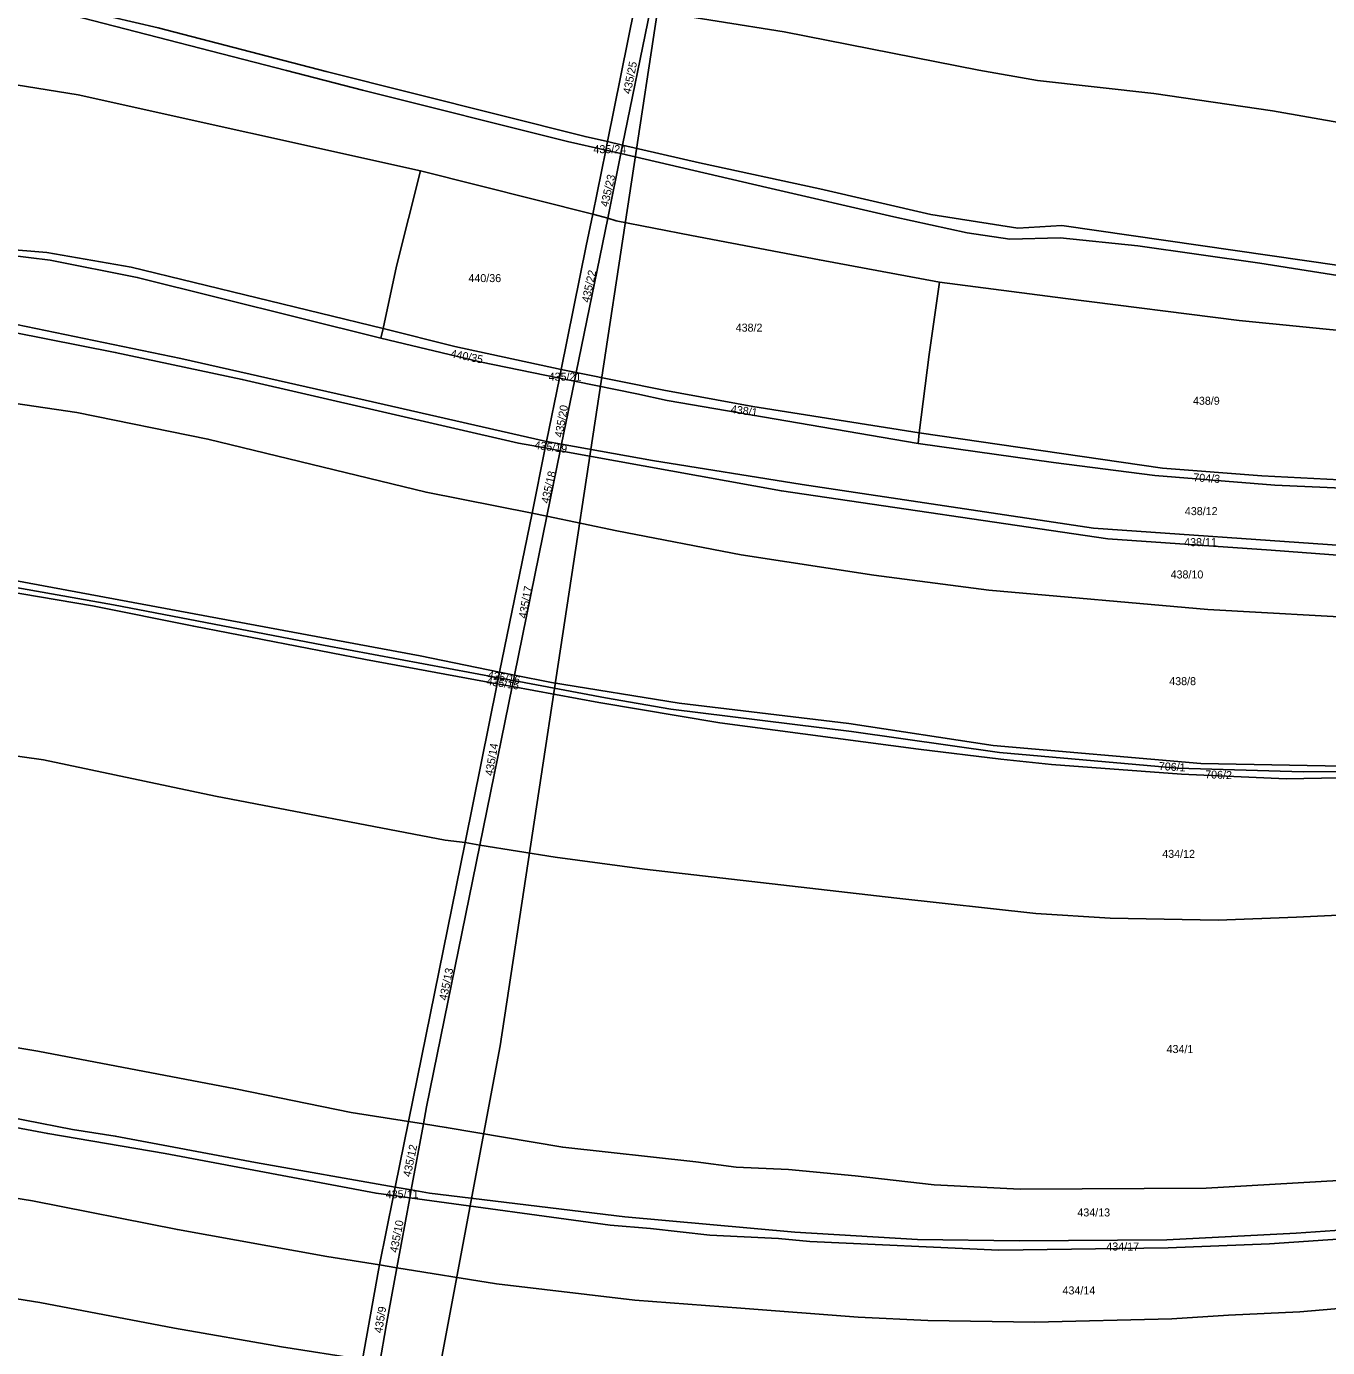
# Model space of a CAD drawing. Extents: x -629983 to -626385, y -1072828 to -1067897.
# Drawn here: x -628398.5 to -627910.7, y -1070643.4 to -1070148.2 of the extents above; entities that cross this region are included whole.
import ezdxf

# ---------------------------------------------------------------- set-up
doc = ezdxf.new("R2010")
doc.units = 0
for name, color, linetype in [('Cesty', 7, 'Continuous'), ('Parcela nároku', 7, 'Continuous'), ('Parcelní číslo', 7, 'Continuous')]:
    doc.layers.add(name, color=color, linetype=linetype)

msp = doc.modelspace()

# ---------------------------------------------------------------- linework, layer by layer
at = {"layer": 'Cesty'}
msp.add_lwpolyline([(-628278.28, -1070828.99), (-628259.19, -1070734.89), (-628220.88, -1070530.25), (-628148.19, -1070051.86), (-628124.88, -1069886.45), (-628121.14, -1069861.86), (-628117.17, -1069852.4), (-628107.82, -1069847.56)], dxfattribs=at)
at = {"layer": 'Parcela nároku'}
for points in [[(-627852.52, -1070193.73), (-627931.37, -1070179.87), (-627975.88, -1070173.38), (-628019.4, -1070168.39), (-628041.43, -1070164.52), (-628114.45, -1070150.16), (-628164.7, -1070142.19), (-628155.63, -1070097.66), (-628130.17, -1070104.96), (-628104.27, -1070109.98), (-628049.15, -1070120.03), (-628018.31, -1070124.92), (-627989.36, -1070130.86), (-627971.32, -1070129.6), (-627953.47, -1070132.37), (-627927.69, -1070135.69), (-627870.76, -1070142.6)], [(-628697.14, -1070105.5), (-628669.73, -1070105.5), (-628645.55, -1070106.32), (-628620.29, -1070107.74), (-628548.7, -1070115.17), (-628493.54, -1070122.93), (-628470.6, -1070125.72), (-628412.78, -1070135.53), (-628392.25, -1070138.74), (-628349.08, -1070148.7), (-628286.11, -1070165.03), (-628189.07, -1070189.45), (-628180.65, -1070191.36), (-628181.31, -1070194.54), (-628195.6, -1070191.34), (-628272.47, -1070172.11), (-628301.01, -1070164.65), (-628377.52, -1070144.99), (-628400.65, -1070140.75), (-628466.36, -1070130.15), (-628560.91, -1070117.14), (-628623.23, -1070110.99), (-628654.47, -1070108.86), (-628697.25, -1070109.21)], [(-628697.25, -1070109.21), (-628654.47, -1070108.86), (-628623.23, -1070110.99), (-628560.91, -1070117.14), (-628466.36, -1070130.15), (-628400.65, -1070140.75), (-628377.52, -1070144.99), (-628301.01, -1070164.65), (-628272.47, -1070172.11), (-628195.6, -1070191.34), (-628181.31, -1070194.54), (-628186.19, -1070218.59), (-628250.78, -1070202.28), (-628379.11, -1070173.77), (-628421.82, -1070167.01), (-628468.03, -1070161.59), (-628516.64, -1070158.65), (-628589.02, -1070154.96), (-628707.96, -1070153.76)], [(-628170.51, -1070141.27), (-628180.65, -1070191.36), (-628189.07, -1070189.45), (-628286.11, -1070165.03), (-628349.08, -1070148.7), (-628392.25, -1070138.74)], [(-627852.52, -1070193.73), (-627931.37, -1070179.87), (-627975.88, -1070173.38), (-628019.4, -1070168.39), (-628041.43, -1070164.52), (-628114.45, -1070150.16), (-628164.7, -1070142.19), (-628175, -1070192.75), (-628146.13, -1070199.31), (-628101.07, -1070209.03), (-628059.41, -1070218.64), (-628026.82, -1070223.84), (-628010.32, -1070222.78), (-627867.35, -1070243.48)], [(-627872.06, -1070246.99), (-627936.13, -1070236.87), (-627981.78, -1070230.48), (-628010.99, -1070227.44), (-628029.83, -1070227.91), (-628045.76, -1070225.52), (-628073.29, -1070219.58), (-628120.92, -1070208.51), (-628175.63, -1070195.81), (-628180.56, -1070220), (-628177.36, -1070221.02), (-628149.11, -1070226.54), (-628101.18, -1070235.71), (-628056.15, -1070244.07), (-628008.92, -1070250.2), (-627943.87, -1070258.43), (-627852.12, -1070267.55)], [(-627872.06, -1070246.99), (-627936.13, -1070236.87), (-627981.78, -1070230.48), (-628010.99, -1070227.44), (-628029.83, -1070227.91), (-628045.76, -1070225.52), (-628073.29, -1070219.58), (-628120.92, -1070208.51), (-628175.63, -1070195.81), (-628175, -1070192.75), (-628146.13, -1070199.31), (-628101.07, -1070209.03), (-628059.41, -1070218.64), (-628026.82, -1070223.84), (-628010.32, -1070222.78), (-627867.35, -1070243.48)], [(-628706.32, -1070228.2), (-628676.43, -1070226.93), (-628641.43, -1070225.97), (-628548.86, -1070228.15), (-628496.37, -1070229.17), (-628472.75, -1070229.44), (-628405.88, -1070233.81), (-628389.6, -1070235.8), (-628356.96, -1070242.24), (-628265.56, -1070264.98), (-628228.53, -1070273.87), (-628198.66, -1070279.99), (-628203.49, -1070303.75), (-628271.49, -1070288.24), (-628340.63, -1070272.61), (-628402.14, -1070259.92), (-628441.52, -1070255.31), (-628483.88, -1070253.57), (-628553.7, -1070253.06), (-628664.36, -1070255.18), (-628699.47, -1070256.47)], [(-628718.01, -1070289.28), (-628654.01, -1070286.5), (-628619.64, -1070286.58), (-628545.91, -1070283.54), (-628494.55, -1070281.54), (-628438.22, -1070284.3), (-628379.6, -1070292.88), (-628330.41, -1070302.87), (-628248.65, -1070322.77), (-628208.94, -1070330.57), (-628203.99, -1070306.2), (-628214, -1070304.38), (-628317.59, -1070280.52), (-628365.18, -1070270.35), (-628403.66, -1070262.78), (-628433.52, -1070259), (-628452.82, -1070257.33), (-628510.86, -1070255.71), (-628594.38, -1070256.49), (-628664.77, -1070258.22), (-628698.91, -1070259.7)], [(-628718.01, -1070289.28), (-628654.01, -1070286.5), (-628619.64, -1070286.58), (-628545.91, -1070283.54), (-628494.55, -1070281.54), (-628438.22, -1070284.3), (-628379.6, -1070292.88), (-628330.41, -1070302.87), (-628248.65, -1070322.77), (-628208.94, -1070330.57), (-628221.07, -1070390.29), (-628250.91, -1070384.06), (-628402.82, -1070355.87), (-628428.44, -1070352.58), (-628471.84, -1070348.52), (-628506.06, -1070348.62), (-628535.45, -1070349.59), (-628587.84, -1070353.27), (-628641.1, -1070355.58), (-628669.24, -1070357.52), (-628669.03, -1070360), (-628668.96, -1070361.81), (-628716.27, -1070364.26)], [(-628426.01, -1070356.51), (-628373.76, -1070365.31), (-628335.77, -1070373.02), (-628271.33, -1070385.43), (-628221.94, -1070394.59), (-628234.03, -1070454.14), (-628241.48, -1070453.19), (-628327.58, -1070436.69), (-628392.12, -1070423.1), (-628443.67, -1070415.82)], [(-627830.1, -1070477.74), (-627922.31, -1070482.11), (-627951.66, -1070483.18), (-627992.24, -1070482.47), (-628020, -1070480.64), (-628072.18, -1070474.9), (-628166.82, -1070464.1), (-628200.27, -1070459.64), (-628228.46, -1070455.05), (-628216.36, -1070395.63), (-628183.83, -1070401.66), (-628138.5, -1070409.17), (-628064.04, -1070419.12), (-628033.19, -1070422.86), (-628014.16, -1070424.89), (-627965.43, -1070428.42), (-627926.22, -1070430.23), (-627866.68, -1070429.07)], [(-628437.81, -1070524.99), (-628394.14, -1070532.32), (-628320.09, -1070546.38), (-628276.71, -1070555.23), (-628255.21, -1070558.63), (-628234.03, -1070454.14), (-628241.48, -1070453.19), (-628327.58, -1070436.69), (-628392.12, -1070423.1), (-628443.67, -1070415.82)], [(-627830.1, -1070477.74), (-627922.31, -1070482.11), (-627951.66, -1070483.18), (-627992.24, -1070482.47), (-628020, -1070480.64), (-628072.18, -1070474.9), (-628166.82, -1070464.1), (-628200.27, -1070459.64), (-628228.46, -1070455.05), (-628248.46, -1070553.17), (-628249.63, -1070559.51), (-628241.09, -1070560.87), (-628197.41, -1070568.33), (-628147.55, -1070573.73), (-628132.4, -1070575.73), (-628112.77, -1070576.7), (-628087.81, -1070579.06), (-628058.23, -1070582.4), (-628025.88, -1070584.04), (-627956.15, -1070583.61), (-627880.67, -1070579.28)], [(-628437.81, -1070524.99), (-628394.14, -1070532.32), (-628320.09, -1070546.38), (-628276.71, -1070555.23), (-628255.21, -1070558.63), (-628260.2, -1070583.25), (-628312.58, -1070573.99), (-628365.16, -1070564.13), (-628381.21, -1070561.65), (-628434.99, -1070551.16)], [(-628452.48, -1070551.49), (-628390.46, -1070563.16), (-628346.52, -1070570.66), (-628267.4, -1070585.55), (-628260.85, -1070586.44), (-628266.12, -1070612.44), (-628285.86, -1070609.24), (-628341.85, -1070599.18), (-628396.16, -1070588.43), (-628461.18, -1070577.86)], [(-627886.17, -1070598.06), (-627922.42, -1070600.5), (-627971, -1070603.08), (-628026.25, -1070603.41), (-628064.48, -1070602.87), (-628110.42, -1070600.1), (-628174.13, -1070594.4), (-628247.39, -1070585.51), (-628254.21, -1070584.31), (-628249.63, -1070559.51), (-628241.09, -1070560.87), (-628197.41, -1070568.33), (-628147.55, -1070573.73), (-628132.4, -1070575.73), (-628112.77, -1070576.7), (-628087.81, -1070579.06), (-628058.23, -1070582.4), (-628025.88, -1070584.04), (-627956.15, -1070583.61), (-627880.67, -1070579.28)], [(-628461.18, -1070577.86), (-628396.16, -1070588.43), (-628341.85, -1070599.18), (-628285.86, -1070609.24), (-628266.12, -1070612.44), (-628266.51, -1070614.38), (-628272.51, -1070647.92), (-628302.84, -1070643.17), (-628342.94, -1070636.07), (-628393.47, -1070626.54), (-628442.96, -1070618.68)], [(-627879.61, -1070600.88), (-627932.47, -1070604.52), (-627970.45, -1070606.06), (-628033.95, -1070606.87), (-628104.75, -1070603.7), (-628116.52, -1070602.55), (-628142.22, -1070601.28), (-628164.51, -1070598.79), (-628179.7, -1070597.46), (-628254.76, -1070587.27), (-628259.61, -1070613.49), (-628222.19, -1070619.55), (-628170.37, -1070625.67), (-628130.69, -1070628.69), (-628086.68, -1070632.01), (-628060.6, -1070633.22), (-628020.49, -1070633.87), (-627969.04, -1070632.64), (-627947.86, -1070631.28), (-627921.14, -1070630.03), (-627870.01, -1070625.59)], [(-628272.51, -1070647.92), (-628302.84, -1070643.17), (-628342.94, -1070636.07), (-628393.47, -1070626.54), (-628442.96, -1070618.68), (-628464.05, -1070615.64), (-628486.47, -1070613.85), (-628509.5, -1070612.76), (-628545.74, -1070615.25), (-628593.51, -1070623.9), (-628639.5, -1070632.73), (-628651.77, -1070635.89), (-628709.71, -1070648.87)], [(-627903.25, -1070656.94), (-627969.61, -1070662.08), (-628010.4, -1070663.68), (-628050.69, -1070664.96), (-628095.77, -1070665.28), (-628130.82, -1070663.87), (-628192.91, -1070658.82), (-628232.19, -1070654.23), (-628265.99, -1070648.94), (-628263.64, -1070635.31), (-628259.61, -1070613.49), (-628222.19, -1070619.55), (-628170.37, -1070625.67), (-628130.69, -1070628.69), (-628086.68, -1070632.01), (-628060.6, -1070633.22), (-628020.49, -1070633.87), (-627969.04, -1070632.64), (-627947.86, -1070631.28), (-627921.14, -1070630.03), (-627870.01, -1070625.59)]]:
    msp.add_lwpolyline(points, dxfattribs=at)
for points in [[(-628164.7, -1070142.19), (-628170.51, -1070141.27), (-628180.65, -1070191.36), (-628175, -1070192.75)], [(-628379.11, -1070173.77), (-628250.78, -1070202.28), (-628259.79, -1070238.1), (-628264.77, -1070261.35), (-628359.24, -1070238.39), (-628390.8, -1070232.96), (-628442.26, -1070228.67), (-628466.38, -1070227.31), (-628536.07, -1070225.95), (-628573.86, -1070225.34), (-628641.41, -1070224.05), (-628696.79, -1070225.17), (-628706.68, -1070225.65), (-628706.32, -1070228.2), (-628709.82, -1070228.71), (-628714.51, -1070190.29), (-628718.85, -1070154.67), (-628707.96, -1070153.76), (-628589.02, -1070154.96), (-628516.64, -1070158.65), (-628468.03, -1070161.59), (-628421.82, -1070167.01)], [(-628181.31, -1070194.54), (-628180.65, -1070191.36), (-628175, -1070192.75), (-628175.63, -1070195.81)], [(-628175.63, -1070195.81), (-628181.31, -1070194.54), (-628186.19, -1070218.59), (-628180.56, -1070220)], [(-628250.78, -1070202.28), (-628186.19, -1070218.59), (-628188.6, -1070230.48), (-628198.03, -1070276.73), (-628237.85, -1070268.2), (-628264.77, -1070261.35), (-628259.79, -1070238.1)], [(-628188.6, -1070230.48), (-628186.19, -1070218.59), (-628180.56, -1070220), (-628192.38, -1070277.89), (-628198.03, -1070276.73)], [(-628101.18, -1070235.71), (-628056.15, -1070244.07), (-628060.11, -1070271.11), (-628063.81, -1070300.51), (-628126.17, -1070290.63), (-628159.48, -1070284.58), (-628192.38, -1070277.89), (-628180.56, -1070220), (-628177.36, -1070221.02), (-628149.11, -1070226.54)], [(-628573.86, -1070225.34), (-628641.41, -1070224.05), (-628696.79, -1070225.17), (-628706.68, -1070225.65), (-628706.32, -1070228.2), (-628676.43, -1070226.93), (-628641.43, -1070225.97), (-628548.86, -1070228.15), (-628496.37, -1070229.17), (-628472.75, -1070229.44), (-628405.88, -1070233.81), (-628389.6, -1070235.8), (-628356.96, -1070242.24), (-628265.56, -1070264.98), (-628264.77, -1070261.35), (-628359.24, -1070238.39), (-628390.8, -1070232.96), (-628442.26, -1070228.67), (-628466.38, -1070227.31), (-628536.07, -1070225.95)], [(-628060.11, -1070271.11), (-628056.15, -1070244.07), (-628008.92, -1070250.2), (-627943.87, -1070258.43), (-627852.12, -1070267.55), (-627857.41, -1070320.6), (-627935.31, -1070316.64), (-627972.58, -1070313.71), (-628063.81, -1070300.51)], [(-628340.63, -1070272.61), (-628271.49, -1070288.24), (-628203.49, -1070303.75), (-628203.99, -1070306.2), (-628214, -1070304.38), (-628317.59, -1070280.52), (-628365.18, -1070270.35), (-628403.66, -1070262.78), (-628433.52, -1070259), (-628452.82, -1070257.33), (-628510.86, -1070255.71), (-628594.38, -1070256.49), (-628664.77, -1070258.22), (-628698.91, -1070259.7), (-628699.47, -1070256.47), (-628664.36, -1070255.18), (-628553.7, -1070253.06), (-628483.88, -1070253.57), (-628441.52, -1070255.31), (-628402.14, -1070259.92)], [(-628264.77, -1070261.35), (-628237.85, -1070268.2), (-628198.03, -1070276.73), (-628198.66, -1070279.99), (-628228.53, -1070273.87), (-628265.56, -1070264.98)], [(-628198.66, -1070279.99), (-628193.03, -1070281.15), (-628197.85, -1070304.82), (-628203.49, -1070303.75)], [(-628198.03, -1070276.73), (-628198.66, -1070279.99), (-628193.03, -1070281.15), (-628192.38, -1070277.89)], [(-628159.48, -1070284.58), (-628126.17, -1070290.63), (-628063.81, -1070300.51), (-628064.17, -1070304.46), (-628158.28, -1070288.4), (-628169.7, -1070285.94), (-628193.03, -1070281.15), (-628192.38, -1070277.89)], [(-627975.41, -1070316.56), (-628013.39, -1070311.63), (-628064.17, -1070304.46), (-628158.28, -1070288.4), (-628169.7, -1070285.94), (-628193.03, -1070281.15), (-628197.85, -1070304.82), (-628163.72, -1070310.89), (-628107.67, -1070319.94), (-627998.49, -1070336.29), (-627905.29, -1070342.7), (-627827.64, -1070345.16), (-627715.35, -1070349), (-627667.5, -1070351.19), (-627663.96, -1070345.7), (-627647.13, -1070331.03), (-627719.77, -1070327.49), (-627789.19, -1070324.83), (-627857.63, -1070323.4), (-627930.45, -1070320.12)], [(-628203.99, -1070306.2), (-628203.49, -1070303.75), (-628197.85, -1070304.82), (-628198.34, -1070307.23)], [(-627998.49, -1070336.29), (-627905.29, -1070342.7), (-627827.64, -1070345.16), (-627715.35, -1070349), (-627667.5, -1070351.19), (-627669.14, -1070353.74), (-627747.72, -1070351.32), (-627834.23, -1070347.87), (-627862.19, -1070347.87), (-627903.57, -1070346.68), (-627931.89, -1070344.45), (-627993.13, -1070340.27), (-628115.46, -1070322.29), (-628198.34, -1070307.23), (-628197.85, -1070304.82), (-628163.72, -1070310.89), (-628107.67, -1070319.94)], [(-627935.31, -1070316.64), (-627857.41, -1070320.6), (-627857.63, -1070323.4), (-627930.45, -1070320.12), (-627975.41, -1070316.56), (-628013.39, -1070311.63), (-628064.17, -1070304.46), (-628063.81, -1070300.51), (-627972.58, -1070313.71)], [(-628208.94, -1070330.57), (-628203.99, -1070306.2), (-628198.34, -1070307.23), (-628203.34, -1070331.74)], [(-627903.57, -1070346.68), (-627931.89, -1070344.45), (-627993.13, -1070340.27), (-628115.46, -1070322.29), (-628198.34, -1070307.23), (-628203.34, -1070331.74), (-628177.12, -1070337.23), (-628130.58, -1070346.23), (-628080.75, -1070353.83), (-628037.7, -1070359.47), (-627955.53, -1070366.72), (-627892.97, -1070370.2), (-627840.14, -1070371.16), (-627807.49, -1070371.09), (-627701.48, -1070374.12), (-627693.61, -1070374.29), (-627674.98, -1070362.82), (-627669.14, -1070353.74), (-627747.72, -1070351.32), (-627834.23, -1070347.87), (-627862.19, -1070347.87)], [(-628221.07, -1070390.29), (-628208.94, -1070330.57), (-628203.34, -1070331.74), (-628215.5, -1070391.4)], [(-628177.12, -1070337.23), (-628130.58, -1070346.23), (-628080.75, -1070353.83), (-628037.7, -1070359.47), (-627955.53, -1070366.72), (-627892.97, -1070370.2), (-627840.14, -1070371.16), (-627807.49, -1070371.09), (-627701.48, -1070374.12), (-627693.61, -1070374.29), (-627709.42, -1070384.02), (-627728.14, -1070388.04), (-627744.07, -1070422.21), (-627744.1, -1070423.1), (-627756.84, -1070422.46), (-627773.24, -1070422.4), (-627898.31, -1070425.56), (-627958.23, -1070424.48), (-628036.03, -1070417.71), (-628090.14, -1070409.45), (-628153.81, -1070401.82), (-628201.61, -1070394.13), (-628215.5, -1070391.4), (-628203.34, -1070331.74)], [(-628428.44, -1070352.58), (-628402.82, -1070355.87), (-628250.91, -1070384.06), (-628221.07, -1070390.29), (-628221.49, -1070392.37), (-628287.16, -1070380.06), (-628365.88, -1070365.05), (-628421.56, -1070355.07), (-628473.35, -1070350.78), (-628501.58, -1070350.88), (-628529.06, -1070351.77), (-628592.68, -1070355.96), (-628640.63, -1070358.32), (-628669.03, -1070360), (-628669.24, -1070357.52), (-628641.1, -1070355.58), (-628587.84, -1070353.27), (-628535.45, -1070349.59), (-628506.06, -1070348.62), (-628471.84, -1070348.52)], [(-628640.63, -1070358.32), (-628592.68, -1070355.96), (-628529.06, -1070351.77), (-628501.58, -1070350.88), (-628473.35, -1070350.78), (-628421.56, -1070355.07), (-628365.88, -1070365.05), (-628287.16, -1070380.06), (-628221.49, -1070392.37), (-628221.94, -1070394.59), (-628271.33, -1070385.43), (-628335.77, -1070373.02), (-628373.76, -1070365.31), (-628426.01, -1070356.51), (-628441.94, -1070355.07), (-628474.42, -1070352.94), (-628507.41, -1070353.04), (-628564.78, -1070355.96), (-628612.59, -1070359.43), (-628668.96, -1070361.81), (-628669.03, -1070360)], [(-628221.94, -1070394.59), (-628221.49, -1070392.37), (-628215.91, -1070393.41), (-628216.36, -1070395.63)], [(-628221.49, -1070392.37), (-628221.07, -1070390.29), (-628215.5, -1070391.4), (-628215.91, -1070393.41)], [(-627919.9, -1070427.62), (-627858.09, -1070426.97), (-627808.9, -1070425.55), (-627769.34, -1070425.27), (-627744.2, -1070425.6), (-627744.29, -1070427.85), (-627775, -1070427.43), (-627820.12, -1070428.07), (-627844.34, -1070429.01), (-627866.68, -1070429.07), (-627926.22, -1070430.23), (-627965.43, -1070428.42), (-628014.16, -1070424.89), (-628033.19, -1070422.86), (-628064.04, -1070419.12), (-628138.5, -1070409.17), (-628183.83, -1070401.66), (-628216.36, -1070395.63), (-628215.91, -1070393.41), (-628181.33, -1070399.89), (-628156.9, -1070404.07), (-628089.12, -1070412.47), (-628033.7, -1070420.29), (-627966.92, -1070426.19)], [(-627958.23, -1070424.48), (-627898.31, -1070425.56), (-627773.24, -1070422.4), (-627756.84, -1070422.46), (-627744.1, -1070423.1), (-627744.2, -1070425.6), (-627769.34, -1070425.27), (-627808.9, -1070425.55), (-627858.09, -1070426.97), (-627919.9, -1070427.62), (-627966.92, -1070426.19), (-628033.7, -1070420.29), (-628089.12, -1070412.47), (-628156.9, -1070404.07), (-628181.33, -1070399.89), (-628215.91, -1070393.41), (-628215.5, -1070391.4), (-628201.61, -1070394.13), (-628153.81, -1070401.82), (-628090.14, -1070409.45), (-628036.03, -1070417.71)], [(-628221.94, -1070394.59), (-628216.36, -1070395.63), (-628228.46, -1070455.05), (-628234.03, -1070454.14)], [(-628228.46, -1070455.05), (-628234.03, -1070454.14), (-628255.21, -1070558.63), (-628249.63, -1070559.51), (-628248.46, -1070553.17)], [(-628559.2, -1070550.25), (-628515.21, -1070544.37), (-628495.07, -1070544.02), (-628473.67, -1070545), (-628434.99, -1070551.16), (-628381.21, -1070561.65), (-628365.16, -1070564.13), (-628312.58, -1070573.99), (-628260.2, -1070583.25), (-628260.85, -1070586.44), (-628267.4, -1070585.55), (-628346.52, -1070570.66), (-628390.46, -1070563.16), (-628452.48, -1070551.49), (-628472.28, -1070548.61), (-628486.84, -1070547.54), (-628516.41, -1070547.02), (-628574.16, -1070554.81), (-628574.27, -1070553.16)], [(-628260.2, -1070583.25), (-628255.21, -1070558.63), (-628249.63, -1070559.51), (-628254.21, -1070584.31)], [(-628266.12, -1070612.44), (-628260.85, -1070586.44), (-628254.76, -1070587.27), (-628259.61, -1070613.49)], [(-628260.85, -1070586.44), (-628260.2, -1070583.25), (-628254.21, -1070584.31), (-628254.76, -1070587.27)], [(-628026.25, -1070603.41), (-627971, -1070603.08), (-627922.42, -1070600.5), (-627886.17, -1070598.06), (-627830.32, -1070593.77), (-627772.67, -1070589.48), (-627746.55, -1070586.97), (-627749.28, -1070591.09), (-627870.03, -1070600.31), (-627879.61, -1070600.88), (-627932.47, -1070604.52), (-627970.45, -1070606.06), (-628033.95, -1070606.87), (-628104.75, -1070603.7), (-628116.52, -1070602.55), (-628142.22, -1070601.28), (-628164.51, -1070598.79), (-628179.7, -1070597.46), (-628254.76, -1070587.27), (-628254.21, -1070584.31), (-628247.39, -1070585.51), (-628174.13, -1070594.4), (-628110.42, -1070600.1), (-628064.48, -1070602.87)], [(-628272.51, -1070647.92), (-628266.51, -1070614.38), (-628266.12, -1070612.44), (-628259.61, -1070613.49), (-628263.64, -1070635.31), (-628265.99, -1070648.94)]]:
    msp.add_lwpolyline(points, close=True, dxfattribs=at)

# ---------------------------------------------------------------- texts
at = {"layer": 'Parcelní číslo'}
for s, rotation, p in [('435/25', 78.4231, (-628171.98, -1070173.7)), ('435/23', 77.0822, (-628180.44, -1070216.03)), ('435/22', 77.7929, (-628187.45, -1070251.88)), ('440/35', 348.5498, (-628239.67, -1070272.14)), ('435/20', 79.7891, (-628197.57, -1070302.46)), ('438/1', 352.0823, (-628134.55, -1070293.02)), ('435/19', 352.4142, (-628208.17, -1070306.48)), ('435/18', 76.9861, (-628202.68, -1070327.21)), ('704/3', 356.2472, (-627961.11, -1070318.66)), ('435/17', 79.5923, (-628211.06, -1070370.28)), ('435/15', 351.4498, (-628226.15, -1070394.97)), ('435/16', 349.9025, (-628225.78, -1070392.63)), ('435/14', 80.3504, (-628223.65, -1070429.27)), ('706/1', 356.7362, (-627974.03, -1070426.9)), ('706/2', 358.1868, (-627956.62, -1070430.01)), ('435/13', 78.3243, (-628240.89, -1070513.47)), ('435/12', 78.1754, (-628254.44, -1070579.64)), ('435/10', 79.0849, (-628259.37, -1070608.02)), ('435/9', 80.3574, (-628265.21, -1070638.17))]:
    msp.add_text(s, height=3, rotation=rotation, dxfattribs=at).set_placement(p)
for s, p in [('435/24', (-628185.91, -1070195.69)), ('440/36', (-628232.78, -1070244.02)), ('438/2', (-628132.59, -1070262.59)), ('435/21', (-628202.7, -1070280.98)), ('438/9', (-627961.16, -1070290)), ('438/12', (-627964.2, -1070331.37)), ('438/11', (-627964.46, -1070343)), ('438/10', (-627969.54, -1070355.1)), ('438/8', (-627970.05, -1070395.1)), ('434/12', (-627972.67, -1070459.84)), ('434/1', (-627971.05, -1070533.01)), ('435/11', (-628263.77, -1070587.41)), ('434/13', (-628004.49, -1070594.25)), ('434/17', (-627993.62, -1070607.02)), ('434/14', (-628010.05, -1070623.47))]:
    msp.add_text(s, height=3, dxfattribs=at).set_placement(p)

doc.saveas('drawing.dxf')
